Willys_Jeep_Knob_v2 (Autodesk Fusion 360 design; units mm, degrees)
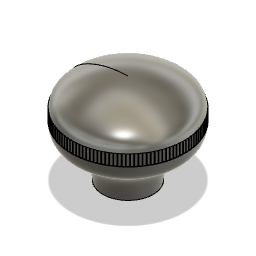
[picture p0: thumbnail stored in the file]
sketch "Sketch1" plane through (0, 0, 0) normal (0, 0, 1) x axis (1, 0, 0)
  line L1 (0, 26.86) -> (0, 2.05)
  line L2 (0, 19.47) -> (0, 25.86)
  line L3 (-15.76, 16.31) -> (-15.76, 19.47)
  curve K1 (-15.76, 19.47) -> (0, 27.11)
  line L4 (-7, 1.26) -> (-7, 1.05)
  curve K2 (-2.8789, 27.0032) -> (0, 27.11)
  curve K3 (-6.6427, 26.4143) -> (-2.8789, 27.0032)
  curve K4 (-10.0394, 25.1422) -> (-6.6427, 26.4143)
  curve K5 (-13.0742, 23.8163) -> (-10.0394, 25.1422)
  curve K6 (-15.5028, 21.6582) -> (-13.0742, 23.8163)
  curve K7 (-15.5818, 20.267) -> (-15.5028, 21.6582)
  curve K8 (-15.76, 19.47) -> (-15.5818, 20.267)
  line L5 (0, 25.86) -> (0, 26.86)
  line L6 (0, 2.05) -> (0, 26.86)
  line L7 (0, 2.05) -> (0, 27.11)
  line L8 (-7.0162, 2.05) -> (0, 2.05)
  curve K9 (-15.76, 16.31) -> (-7.0162, 2.05)
  curve K10 (-7.0809, 3.6051) -> (-7.0162, 2.05)
  curve K11 (-7.3268, 5.3212) -> (-7.0809, 3.6051)
  curve K12 (-8.1253, 8.0234) -> (-7.3268, 5.3212)
  curve K13 (-11.8902, 10.9717) -> (-8.1253, 8.0234)
  curve K14 (-14.0683, 11.824) -> (-11.8902, 10.9717)
  curve K15 (-15.6555, 13.2694) -> (-14.0683, 11.824)
  curve K16 (-15.7706, 15.7991) -> (-15.6555, 13.2694)
  curve K17 (-15.76, 16.31) -> (-15.7706, 15.7991)
  point P1 (0, 0)
  point P2 (0, 25.86)
  point P3 (0, 19.47)
  point P4 (-15.76, 19.47)
  point P5 (-15.76, 16.31)
  parallel L1 L2
  parallel L2 L5
  horizontal L8
  dimension "d2" distance P1 P2 = 25.86
  dimension "d3" distance P2 P3 = 6.39
  dimension "d4" distance P3 P4 = 15.76 (= "( 31.52 / 2 ) * 1 mm")
  dimension "d5" distance P4 P5 = 3.16
revolve "Revolve3" sketch "Sketch1" AlongAngle 360
work_plane "WorkPlane1" RotateAngle 0
work_plane "WorkPlane2" AlongDistance 0.5
sketch "Sketch3" plane through (-16.26, 17.4237, 0) normal (-1, 0, 0) x axis (0, 0, -1)
sketch "Sketch4" plane through (-15.76, 17.4237, 0) normal (-1, 0, 0) x axis (0, 0, -1)
  line L1 (15.76, 1.1137) -> (-15.76, 1.1137)
  line L2 (15.76, -2.0463) -> (-15.76, -2.0463)
  line L3 (-15.76, -2.0463) -> (15.76, -2.0463)
  line L4 (-15.76, 1.1137) -> (15.76, 1.1137)
  point P5 (15.76, -2.0463)
  point P6 (15.76, -2.0463)
  point P4 (-15.76, -2.0463)
  point P7 (-15.76, -2.0463)
  point P3 (15.76, 1.1137)
  point P8 (15.76, 1.1137)
  point P2 (-15.76, 1.1137)
  point P9 (-15.76, 1.1137)
  coincident P5 P6
  coincident P4 P7
  coincident P3 P8
  coincident P2 P9
split "Split1"
sketch "Sketch5" plane through (0, 19.47, 0) normal (0, 1, 0) x axis (-1, 0, 0)
  circle C1 centre (0, 0) radius 15.76
  circle C2 centre (0, 15.95) radius 0.375
  circle C3 centre (-0.8348, 15.9281) radius 0.375
  circle C4 centre (-1.6672, 15.8626) radius 0.375
  circle C5 centre (-2.4951, 15.7536) radius 0.375
  circle C6 centre (-3.3162, 15.6015) radius 0.375
  circle C7 centre (-4.1282, 15.4065) radius 0.375
  circle C8 centre (-4.9288, 15.1694) radius 0.375
  circle C9 centre (-5.716, 14.8906) radius 0.375
  circle C10 centre (-6.4874, 14.5711) radius 0.375
  circle C11 centre (-7.2411, 14.2116) radius 0.375
  circle C12 centre (-7.975, 13.8131) radius 0.375
  circle C13 centre (-8.687, 13.3768) radius 0.375
  circle C14 centre (-9.3752, 12.9038) radius 0.375
  circle C15 centre (-10.0377, 12.3955) radius 0.375
  circle C16 centre (-10.6726, 11.8532) radius 0.375
  circle C17 centre (-11.2784, 11.2784) radius 0.375
  circle C18 centre (-11.8532, 10.6726) radius 0.375
  circle C19 centre (-12.3955, 10.0377) radius 0.375
  circle C20 centre (-12.9038, 9.3752) radius 0.375
  circle C21 centre (-13.3768, 8.687) radius 0.375
  circle C22 centre (-13.8131, 7.975) radius 0.375
  circle C23 centre (-14.2116, 7.2411) radius 0.375
  circle C24 centre (-14.5711, 6.4874) radius 0.375
  circle C25 centre (-14.8906, 5.716) radius 0.375
  circle C26 centre (-15.1694, 4.9288) radius 0.375
  circle C27 centre (-15.4065, 4.1282) radius 0.375
  circle C28 centre (-15.6015, 3.3162) radius 0.375
  circle C29 centre (-15.7536, 2.4951) radius 0.375
  circle C30 centre (-15.8626, 1.6672) radius 0.375
  circle C31 centre (-15.9281, 0.8348) radius 0.375
  circle C32 centre (-15.95, 0) radius 0.375
  circle C33 centre (-15.9281, -0.8348) radius 0.375
  circle C34 centre (-15.8626, -1.6672) radius 0.375
  circle C35 centre (-15.7536, -2.4951) radius 0.375
  circle C36 centre (-15.6015, -3.3162) radius 0.375
  circle C37 centre (-15.4065, -4.1282) radius 0.375
  circle C38 centre (-15.1694, -4.9288) radius 0.375
  circle C39 centre (-14.8906, -5.716) radius 0.375
  circle C40 centre (-14.5711, -6.4874) radius 0.375
  circle C41 centre (-14.2116, -7.2411) radius 0.375
  circle C42 centre (-13.8131, -7.975) radius 0.375
  circle C43 centre (-13.3768, -8.687) radius 0.375
  circle C44 centre (-12.9038, -9.3752) radius 0.375
  circle C45 centre (-12.3955, -10.0377) radius 0.375
  circle C46 centre (-11.8532, -10.6726) radius 0.375
  circle C47 centre (-11.2784, -11.2784) radius 0.375
  circle C48 centre (-10.6726, -11.8532) radius 0.375
  circle C49 centre (-10.0377, -12.3955) radius 0.375
  circle C50 centre (-9.3752, -12.9038) radius 0.375
  circle C51 centre (-8.687, -13.3768) radius 0.375
  circle C52 centre (-7.975, -13.8131) radius 0.375
  circle C53 centre (-7.2411, -14.2116) radius 0.375
  circle C54 centre (-6.4874, -14.5711) radius 0.375
  circle C55 centre (-5.716, -14.8906) radius 0.375
  circle C56 centre (-4.9288, -15.1694) radius 0.375
  circle C57 centre (-4.1282, -15.4065) radius 0.375
  circle C58 centre (-3.3162, -15.6015) radius 0.375
  circle C59 centre (-2.4951, -15.7536) radius 0.375
  circle C60 centre (-1.6672, -15.8626) radius 0.375
  circle C61 centre (-0.8348, -15.9281) radius 0.375
  circle C62 centre (0, -15.95) radius 0.375
  circle C63 centre (0.8348, -15.9281) radius 0.375
  circle C64 centre (1.6672, -15.8626) radius 0.375
  circle C65 centre (2.4951, -15.7536) radius 0.375
  circle C66 centre (3.3162, -15.6015) radius 0.375
  circle C67 centre (4.1282, -15.4065) radius 0.375
  circle C68 centre (4.9288, -15.1694) radius 0.375
  circle C69 centre (5.716, -14.8906) radius 0.375
  circle C70 centre (6.4874, -14.5711) radius 0.375
  circle C71 centre (7.2411, -14.2116) radius 0.375
  circle C72 centre (7.975, -13.8131) radius 0.375
  circle C73 centre (8.687, -13.3768) radius 0.375
  circle C74 centre (9.3752, -12.9038) radius 0.375
  circle C75 centre (10.0377, -12.3955) radius 0.375
  circle C76 centre (10.6726, -11.8532) radius 0.375
  circle C77 centre (11.2784, -11.2784) radius 0.375
  circle C78 centre (11.8532, -10.6726) radius 0.375
  circle C79 centre (12.3955, -10.0377) radius 0.375
  circle C80 centre (12.9038, -9.3752) radius 0.375
  circle C81 centre (13.3768, -8.687) radius 0.375
  circle C82 centre (13.8131, -7.975) radius 0.375
  circle C83 centre (14.2116, -7.2411) radius 0.375
  circle C84 centre (14.5711, -6.4874) radius 0.375
  circle C85 centre (14.8906, -5.716) radius 0.375
  circle C86 centre (15.1694, -4.9288) radius 0.375
  circle C87 centre (15.4065, -4.1282) radius 0.375
  circle C88 centre (15.6015, -3.3162) radius 0.375
  circle C89 centre (15.7536, -2.4951) radius 0.375
  circle C90 centre (15.8626, -1.6672) radius 0.375
  circle C91 centre (15.9281, -0.8348) radius 0.375
  circle C92 centre (15.95, 0) radius 0.375
  circle C93 centre (15.9281, 0.8348) radius 0.375
  circle C94 centre (15.8626, 1.6672) radius 0.375
  circle C95 centre (15.7536, 2.4951) radius 0.375
  circle C96 centre (15.6015, 3.3162) radius 0.375
  circle C97 centre (15.4065, 4.1282) radius 0.375
  circle C98 centre (15.1694, 4.9288) radius 0.375
  circle C99 centre (14.8906, 5.716) radius 0.375
  circle C100 centre (14.5711, 6.4874) radius 0.375
  circle C101 centre (14.2116, 7.2411) radius 0.375
  circle C102 centre (13.8131, 7.975) radius 0.375
  circle C103 centre (13.3768, 8.687) radius 0.375
  circle C104 centre (12.9038, 9.3752) radius 0.375
  circle C105 centre (12.3955, 10.0377) radius 0.375
  circle C106 centre (11.8532, 10.6726) radius 0.375
  circle C107 centre (11.2784, 11.2784) radius 0.375
  circle C108 centre (10.6726, 11.8532) radius 0.375
  circle C109 centre (10.0377, 12.3955) radius 0.375
  circle C110 centre (9.3752, 12.9038) radius 0.375
  circle C111 centre (8.687, 13.3768) radius 0.375
  circle C112 centre (7.975, 13.8131) radius 0.375
  circle C113 centre (7.2411, 14.2116) radius 0.375
  circle C114 centre (6.4874, 14.5711) radius 0.375
  circle C115 centre (5.716, 14.8906) radius 0.375
  circle C116 centre (4.9288, 15.1694) radius 0.375
  circle C117 centre (4.1282, 15.4065) radius 0.375
  circle C118 centre (3.3162, 15.6015) radius 0.375
  circle C119 centre (2.4951, 15.7536) radius 0.375
  circle C120 centre (1.6672, 15.8626) radius 0.375
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  point P3 (0, 15.95)
  point P4 (0, 0)
  dimension "d13" diameter C2 = 0.75
  dimension "d14" distance P3 P4 = 15.95
  dimension "d16" C-Pattern1-Angle = 360
extrude "Extrude1" cut sketch "Sketch5" against normal blind 3.16
combine "Combine1"
sketch "Sketch6" plane through (0, 1.05, 0) normal (0, -1, 0) x axis (1, 0, 0)
  circle C1 centre (0, 0) radius 7
  circle C2 centre (0, 0) radius 5.475
  point P1 (0, 0)
  point P3 (0, 0)
  coincident P1 P3
  dimension "d19" diameter C2 = 10.95
extrude "Extrude2" cut sketch "Sketch6" profile of C2 against normal blind 15.25
extrude "Extrude3" cut of existing geometry blind -1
